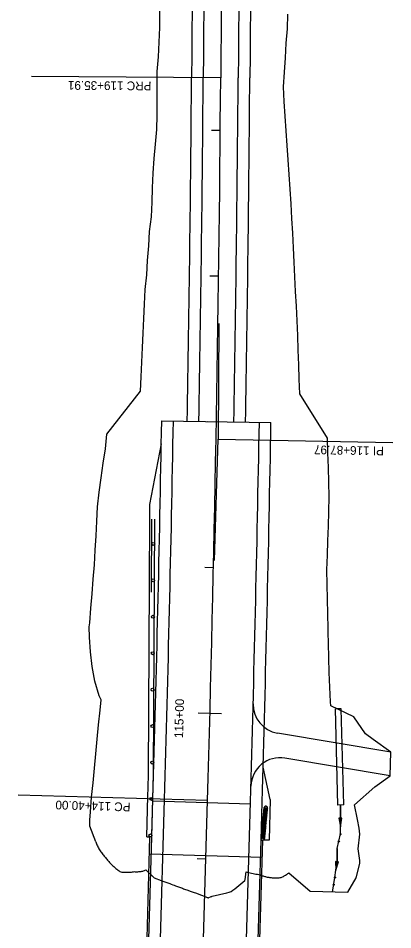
# Model space of a CAD drawing. Extents: x 1441466 to 1476381, y 2042742 to 2057194.
# Drawn here: x 1445981 to 1446238, y 2044108 to 2044733 of the extents above; entities that cross this region are included whole.
import ezdxf

# ---------------------------------------------------------------- set-up
doc = ezdxf.new("R2010")
doc.units = 0
for name, color, linetype in [('Level 43', 7, 'Continuous'), ('R_Bridge', 7, 'Continuous'), ('R_Guardrail', 7, 'Continuous'), ('R_Horz Alg', 7, 'Continuous'), ('R_Horz Alg Annot', 7, 'Continuous'), ('R_Horz Alg Stationing', 7, 'Continuous'), ('R_Impact Attenuator', 7, 'Continuous'), ('R_Proposed Const Limits', 7, 'Continuous'), ('R_Proposed Road', 7, 'Continuous'), ('R_Shld', 7, 'Continuous'), ('R_Special Ditch', 7, 'Continuous')]:
    doc.layers.add(name, color=color, linetype=linetype)

msp = doc.modelspace()

# ---------------------------------------------------------------- linework, layer by layer
at = {"layer": 'Level 43'}
for p, q in [((1446203.02, 2044259.75), (1446199.03, 2044259.65)), ((1446200.63, 2044193.67), (1446199.03, 2044259.65)), ((1446204.63, 2044193.77), (1446203.02, 2044259.75)), ((1446204.63, 2044193.77), (1446200.63, 2044193.67))]:
    msp.add_line(p, q, dxfattribs=at)
at = {"layer": 'R_Bridge'}
for p, q in [((1446140.6, 2044194.41), (1446073.63, 2044196.35)), ((1446068.06, 2044047.95), (1446071.67, 2044171.9)), ((1446069.31, 2044047.92), (1446072.92, 2044171.86)), ((1446072.92, 2044171.86), (1446071.67, 2044171.9)), ((1446144.28, 2044045.74), (1446147.88, 2044169.68)), ((1446145.53, 2044045.7), (1446149.13, 2044169.65)), ((1446147.88, 2044169.68), (1446149.13, 2044169.65)), ((1446148.78, 2044157.65), (1446071.32, 2044159.91))]:
    msp.add_line(p, q, dxfattribs=at)
at = {"layer": 'R_Guardrail'}
msp.add_line((1446072.74, 2044339.83), (1446072.97, 2044389.77), dxfattribs=at)
msp.add_lwpolyline([(1446072.94, 2044172.87), (1446073.67, 2044197.86), (1446074.16, 2044214.97), (1446074.17, 2044215.05), (1446074.97, 2044389.76)], dxfattribs=at)
for centre in [(1446073.89, 2044372.85), (1446073.77, 2044347.85), (1446073.66, 2044322.85), (1446073.55, 2044297.85), (1446073.43, 2044272.85), (1446073.32, 2044247.85), (1446073.2, 2044222.86), (1446072.67, 2044197.89), (1446071.95, 2044172.89)]:
    msp.add_circle(centre, 1, dxfattribs=at)
at = {"layer": 'R_Horz Alg'}
msp.add_line((1446106.5, 2044036.83), (1446111.16, 2044196.76), dxfattribs=at)
for centre, start, end in [((1469037.89, 2044521.83), 178.333333, 179.573112), ((1423202.54, 2044863.34), 358.333333, 359.573112)]:
    msp.add_arc(centre, 22918.31, start, end, dxfattribs=at)
at = {"layer": 'R_Horz Alg Annot'}
for p in [(1446118.96, 2044523.98), (1446115.95, 2044361.46)]:
    msp.add_line(p, (1446118.37, 2044444.62), dxfattribs=at)
for points in [[(1446120.22, 2044692.58), (1445990.22, 2044693.55)], [(1446118.37, 2044444.62), (1446238.35, 2044442.43)], [(1446111.16, 2044196.76), (1445981.21, 2044200.54)]]:
    msp.add_lwpolyline(points, dxfattribs=at)
at = {"layer": 'R_Horz Alg Stationing'}
for points in [[(1446113.92, 2044656.73), (1446119.92, 2044656.67)], [(1446112.8, 2044556.76), (1446118.8, 2044556.68)], [(1446111.24, 2044456.8), (1446117.24, 2044456.69)], [(1446109.25, 2044356.84), (1446115.25, 2044356.71)], [(1446104.83, 2044256.95), (1446120.82, 2044256.53)], [(1446104, 2044156.95), (1446109.99, 2044156.78)]]:
    msp.add_lwpolyline(points, dxfattribs=at)
at = {"layer": 'R_Impact Attenuator'}
for p, q in [((1446148.02, 2044169.8), (1446150.1, 2044192.04)), ((1446150.26, 2044169.59), (1446152.34, 2044191.83)), ((1446151.19, 2044192.94), (1446151.44, 2044192.91))]:
    msp.add_line(p, q, dxfattribs=at)
for centre in [(1446150.6, 2044191.37), (1446151.72, 2044191.27), (1446150.08, 2044185.77), (1446150.18, 2044186.89), (1446150.29, 2044188.01), (1446150.39, 2044189.13), (1446150.5, 2044190.25), (1446151.2, 2044185.67), (1446151.3, 2044186.79), (1446151.41, 2044187.91), (1446151.51, 2044189.03), (1446151.62, 2044190.15), (1446149.45, 2044179.05), (1446149.55, 2044180.17), (1446149.66, 2044181.29), (1446149.76, 2044182.41), (1446149.87, 2044183.53), (1446149.97, 2044184.65), (1446150.57, 2044178.95), (1446150.67, 2044180.07), (1446150.78, 2044181.19), (1446150.88, 2044182.31), (1446150.99, 2044183.43), (1446151.09, 2044184.55), (1446148.92, 2044173.45), (1446149.03, 2044174.57), (1446149.13, 2044175.69), (1446149.24, 2044176.81), (1446149.34, 2044177.93), (1446150.04, 2044173.35), (1446150.15, 2044174.47), (1446150.25, 2044175.59), (1446150.36, 2044176.71), (1446150.46, 2044177.83), (1446148.71, 2044171.21), (1446148.71, 2044171.21), (1446148.82, 2044172.33), (1446149.83, 2044171.11), (1446149.83, 2044171.11), (1446149.94, 2044172.23)]:
    msp.add_circle(centre, 0.563, dxfattribs=at)
for centre, start, end in [((1446151.09, 2044191.94), 84.65511, 174.65511), ((1446151.34, 2044191.92), 354.65511, 84.65511)]:
    msp.add_arc(centre, 1, start, end, dxfattribs=at)
at = {"layer": 'R_Proposed Const Limits'}
for points in [[(1446078.5, 2044727.04), (1446078.45, 2044737.06), (1446078.61, 2044747.08), (1446078.72, 2044757.1), (1446078.88, 2044767.12)], [(1446211.56, 2044254.13), (1446195.84, 2044261.72), (1446195.68, 2044264.59), (1446195.12, 2044274.64), (1446194.74, 2044284.69), (1446194.49, 2044294.73), (1446194.2, 2044304.78), (1446194.04, 2044311.96), (1446193.98, 2044314.82), (1446193.81, 2044324.86), (1446193.59, 2044334.9), (1446193.28, 2044344.95), (1446193.18, 2044354.99), (1446193.5, 2044365.02), (1446193.82, 2044375.05), (1446194.11, 2044385.08), (1446194.4, 2044395.11), (1446194.63, 2044405.14), (1446194.45, 2044415.18), (1446194.21, 2044425.22), (1446193.85, 2044435.26), (1446193.5, 2044445.3), (1446174.54, 2044475.73), (1446174.18, 2044485.76), (1446173.86, 2044495.79), (1446173.5, 2044505.82), (1446173.12, 2044515.85), (1446172.75, 2044525.88), (1446172.22, 2044535.91), (1446171.64, 2044545.95), (1446171.16, 2044555.98), (1446170.68, 2044566.01), (1446170.2, 2044576.04), (1446169.67, 2044586.07), (1446169.14, 2044596.09), (1446168.69, 2044606.12), (1446167.91, 2044616.15), (1446167.3, 2044626.18), (1446166.52, 2044636.21), (1446165.92, 2044646.24), (1446165.15, 2044656.26), (1446164.56, 2044666.29), (1446163.79, 2044676.31), (1446163.38, 2044686.34), (1446164.1, 2044696.34), (1446164.69, 2044706.31), (1446165.11, 2044716.29), (1446165.98, 2044726.26), (1446166.32, 2044736.24)], [(1446034.49, 2044168.54), (1446030.28, 2044179.11), (1446030.36, 2044183.27), (1446030.74, 2044189.1), (1446031.59, 2044199.08), (1446032.61, 2044209.02), (1446033.61, 2044218.96), (1446034.39, 2044228.91), (1446035.43, 2044238.85), (1446036.26, 2044248.8), (1446037.57, 2044258.73), (1446038.06, 2044265.85), (1446036.86, 2044268.72), (1446033.91, 2044278.77), (1446032.01, 2044288.78), (1446030.87, 2044298.78), (1446030.25, 2044308.76), (1446030.03, 2044315.89), (1446030.28, 2044318.73), (1446031.11, 2044328.67), (1446031.93, 2044338.62), (1446032.74, 2044348.57), (1446033.6, 2044358.52), (1446034.12, 2044368.47), (1446034.62, 2044378.43), (1446035.09, 2044388.38), (1446035.67, 2044398.34), (1446036.82, 2044408.28), (1446038.24, 2044418.22), (1446039.63, 2044428.16), (1446041.15, 2044438.1), (1446042.01, 2044448.06), (1446065.18, 2044477.57), (1446065.68, 2044487.54), (1446066.15, 2044497.51), (1446066.61, 2044507.48), (1446067.05, 2044517.46), (1446067.49, 2044527.43), (1446067.92, 2044537.4), (1446068.34, 2044547.37), (1446069.52, 2044557.34), (1446069.89, 2044567.31), (1446070.8, 2044577.28), (1446071.37, 2044587.25), (1446072.74, 2044597.22), (1446073.07, 2044607.19), (1446073.41, 2044617.17), (1446073.8, 2044627.15), (1446074.45, 2044637.12), (1446075.4, 2044647.09), (1446076.4, 2044657.06), (1446076.6, 2044667.04), (1446076.58, 2044677.03), (1446076.7, 2044687.01), (1446076.6, 2044697), (1446077.59, 2044707.01), (1446078.05, 2044717.03), (1446078.5, 2044727.04)], [(1446237.12, 2044229.88), (1446224.86, 2044238.66), (1446219.73, 2044242.46), (1446211.56, 2044254.13)], [(1446207.54, 2044133.93), (1446213.15, 2044143.7), (1446215.7, 2044153.7), (1446215.65, 2044155.71), (1446214.52, 2044163.74), (1446215.66, 2044173.71), (1446215.26, 2044177.89), (1446214.15, 2044183.76), (1446212.01, 2044193.83), (1446225.95, 2044206.31), (1446236.66, 2044213.73)], [(1446034.49, 2044168.54), (1446034.71, 2044167.89), (1446034.97, 2044167.15), (1446035.24, 2044166.43), (1446035.53, 2044165.71), (1446035.84, 2044165), (1446036.22, 2044164.31), (1446036.63, 2044163.65), (1446037.05, 2044162.99), (1446037.48, 2044162.35), (1446037.92, 2044161.72), (1446038.37, 2044161.1), (1446038.82, 2044160.49), (1446039.29, 2044159.9), (1446039.76, 2044159.32), (1446040.24, 2044158.75), (1446040.72, 2044158.19), (1446041.21, 2044157.65), (1446041.67, 2044157.1), (1446042.09, 2044156.53), (1446042.52, 2044155.98), (1446042.96, 2044155.43), (1446043.4, 2044154.9), (1446043.86, 2044154.37), (1446044.32, 2044153.86), (1446044.8, 2044153.35), (1446045.28, 2044152.86), (1446045.77, 2044152.38), (1446046.26, 2044151.91), (1446046.77, 2044151.45), (1446047.28, 2044151), (1446047.8, 2044150.57), (1446048.32, 2044150.14), (1446048.85, 2044149.73), (1446049.39, 2044149.33), (1446049.94, 2044148.94), (1446050.49, 2044148.57), (1446051.04, 2044148.2), (1446051.6, 2044147.85), (1446052.36, 2044147.74), (1446053.14, 2044147.69), (1446053.9, 2044147.65), (1446054.66, 2044147.63), (1446055.41, 2044147.62), (1446056.14, 2044147.62), (1446056.87, 2044147.64), (1446057.58, 2044147.68), (1446058.28, 2044147.72), (1446058.98, 2044147.78), (1446059.66, 2044147.85), (1446060.33, 2044147.93), (1446060.99, 2044148.02), (1446061.58, 2044148), (1446062.16, 2044147.98), (1446062.74, 2044147.98), (1446063.32, 2044148), (1446063.9, 2044148.03), (1446064.47, 2044148.07), (1446065.04, 2044148.14), (1446065.6, 2044148.21), (1446066.15, 2044148.3), (1446066.7, 2044148.4), (1446067.26, 2044148.6), (1446067.82, 2044148.84), (1446068.36, 2044149.09), (1446068.82, 2044149.3)], [(1446068.82, 2044149.29), (1446073.63, 2044144.65), (1446074.11, 2044144.23), (1446074.62, 2044143.86), (1446075.17, 2044143.54), (1446075.75, 2044143.27), (1446078.14, 2044142.31), (1446078.74, 2044142.07), (1446079.34, 2044141.84), (1446079.94, 2044141.62), (1446080.55, 2044141.41), (1446085.32, 2044139.79), (1446086.32, 2044139.45), (1446087.31, 2044139.09), (1446088.3, 2044138.73), (1446089.29, 2044138.36), (1446093.94, 2044136.58), (1446094.68, 2044136.31), (1446095.41, 2044136.04), (1446096.16, 2044135.77), (1446096.9, 2044135.51), (1446099.88, 2044134.49), (1446100.62, 2044134.23), (1446101.36, 2044133.96), (1446102.1, 2044133.69), (1446102.83, 2044133.41), (1446111.06, 2044130.2), (1446111.34, 2044130.12), (1446111.62, 2044130.1), (1446111.9, 2044130.14), (1446112.18, 2044130.25), (1446113.28, 2044130.77), (1446113.56, 2044130.89), (1446113.84, 2044131), (1446114.13, 2044131.09), (1446114.42, 2044131.17), (1446124.47, 2044133.45), (1446125.93, 2044133.87), (1446127.31, 2044134.46), (1446128.6, 2044135.21), (1446129.81, 2044136.13), (1446136.73, 2044142.06), (1446136.77, 2044142.09), (1446136.8, 2044142.13), (1446136.84, 2044142.17), (1446136.87, 2044142.21), (1446137, 2044142.37), (1446137.03, 2044142.41), (1446137.05, 2044142.45), (1446137.07, 2044142.5), (1446137.08, 2044142.55), (1446137.79, 2044147.81)], [(1446137.79, 2044147.81), (1446138.42, 2044147.58), (1446139.42, 2044147.38), (1446140.41, 2044147.19), (1446141.4, 2044146.99), (1446142.4, 2044146.8), (1446143.39, 2044146.6), (1446144.39, 2044146.41), (1446145.38, 2044146.21), (1446146.38, 2044146.02), (1446147.37, 2044145.82), (1446147.39, 2044145.82), (1446147.41, 2044145.81), (1446147.43, 2044145.81), (1446147.82, 2044145.63), (1446148.32, 2044145.44), (1446148.83, 2044145.26), (1446149.35, 2044145.09), (1446149.87, 2044144.92), (1446150.4, 2044144.76), (1446150.94, 2044144.61), (1446151.49, 2044144.47), (1446152.04, 2044144.34), (1446152.6, 2044144.23), (1446153.17, 2044144.14), (1446153.74, 2044144.05), (1446154.31, 2044143.97), (1446154.89, 2044143.91), (1446155.48, 2044143.85), (1446156.07, 2044143.81), (1446156.67, 2044143.78), (1446157.27, 2044143.76), (1446157.88, 2044143.75), (1446158.49, 2044143.76), (1446159.11, 2044143.77), (1446159.73, 2044143.8), (1446160.35, 2044143.85), (1446160.98, 2044143.9), (1446161.61, 2044143.97), (1446162.17, 2044144.18), (1446162.7, 2044144.46), (1446163.22, 2044144.76), (1446163.74, 2044145.06), (1446164.26, 2044145.37), (1446164.77, 2044145.68), (1446165.28, 2044146), (1446165.78, 2044146.33), (1446166.27, 2044146.67), (1446166.76, 2044147.02), (1446166.97, 2044147.17)], [(1446166.97, 2044147.17), (1446181.71, 2044134.68), (1446207.54, 2044133.93)]]:
    msp.add_lwpolyline(points, dxfattribs=at)
at = {"layer": 'R_Proposed Road'}
for p, q in [((1446079.75, 2044457.36), (1446154.74, 2044456.02)), ((1446237.12, 2044229.88), (1446159.18, 2044242.99)), ((1446236.66, 2044213.73), (1446237.12, 2044229.88)), ((1446236.66, 2044213.73), (1446164.27, 2044225.91)), ((1446072.92, 2044171.86), (1446073.67, 2044197.85)), ((1446077.01, 2044037.69), (1446081.67, 2044197.62)), ((1446135.99, 2044035.97), (1446140.64, 2044195.9)), ((1446147.88, 2044169.68), (1446148.64, 2044195.67))]:
    msp.add_line(p, q, dxfattribs=at)
for centre, radius, start, end in [((1469037.89, 2044521.83), 22938.31, 178.333333, 179.573112), ((1469037.89, 2044521.83), 22930.31, 178.333333, 179.573112), ((1469037.89, 2044521.83), 22906.31, 178.333333, 179.573112), ((1469037.89, 2044521.83), 22898.31, 178.333333, 179.573112), ((1423202.54, 2044863.34), 22898.31, 358.983333, 359.573112), ((1423202.54, 2044863.34), 22906.31, 358.983333, 359.573112), ((1423202.54, 2044863.34), 22930.31, 358.983333, 359.573112), ((1423202.54, 2044863.34), 22938.31, 358.983333, 359.573112), ((1423202.54, 2044863.34), 22880.81, 358.333333, 358.983333), ((1423202.54, 2044863.34), 22888.81, 358.333333, 358.983333), ((1423202.54, 2044863.34), 22947.81, 358.333333, 358.983333), ((1423202.54, 2044863.34), 22955.81, 358.333333, 358.983333), ((1446162.5, 2044262.72), 20, 178.50152, 260.44833), ((1446160.95, 2044206.19), 20, 80.44833, 178.36045)]:
    msp.add_arc(centre, radius, start, end, dxfattribs=at)
at = {"layer": 'R_Shld'}
for p, q in [((1446071.67, 2044399.76), (1446079.46, 2044441.41)), ((1446070.67, 2044215.07), (1446071.47, 2044389.78)), ((1446154.2, 2044197.51), (1446149.33, 2044219.71)), ((1446069.42, 2044171.97), (1446070.23, 2044199.95)), ((1446154.2, 2044197.51), (1446153.38, 2044169.52)), ((1446069.42, 2044171.97), (1446071.67, 2044171.9)), ((1446153.38, 2044169.52), (1446149.13, 2044169.65))]:
    msp.add_line(p, q, dxfattribs=at)
for radius, start, end in [(22873.81, 358.808708, 358.833708), (22877.31, 358.333333, 358.371208)]:
    msp.add_arc((1423202.6, 2044865.33), radius, start, end, dxfattribs=at)
at = {"layer": 'R_Special Ditch'}
for p, q in [((1446203.48, 2044184.71), (1446201.37, 2044184.72)), ((1446201.37, 2044184.72), (1446202.42, 2044178.71)), ((1446202.42, 2044178.71), (1446203.48, 2044184.71)), ((1446201.15, 2044154.77), (1446199.06, 2044155.05)), ((1446199.06, 2044155.05), (1446199.3, 2044148.96)), ((1446199.3, 2044148.96), (1446201.15, 2044154.77))]:
    msp.add_line(p, q, dxfattribs=at)
for points in [[(1446196.91, 2044133.96), (1446198.62, 2044143.95), (1446199.98, 2044153.97), (1446200.23, 2044156.09), (1446200.27, 2044164), (1446202.4, 2044173.94), (1446202.41, 2044178.32), (1446202.43, 2044184.16), (1446202.43, 2044193.71)], [(1446202.43, 2044193.71), (1446202.43, 2044184.16), (1446202.42, 2044178.71)], [(1446200.27, 2044163.9), (1446200.23, 2044156.09), (1446199.98, 2044153.97), (1446199.3, 2044148.96)], [(1446200.27, 2044163.94), (1446200.27, 2044163.9)], [(1446196.94, 2044134.11), (1446196.91, 2044133.96)], [(1446196.94, 2044134.15), (1446196.94, 2044134.11)]]:
    msp.add_lwpolyline(points, dxfattribs=at)
for centre in [(1446202.39, 2044173.71), (1446201.34, 2044168.81), (1446198.66, 2044144), (1446197.82, 2044139.06)]:
    msp.add_circle(centre, 0.375, dxfattribs=at)

# ---------------------------------------------------------------- texts
at = {"layer": 'R_Horz Alg Annot'}
for s, rotation, p in [('PRC 119+35.91', 179.57311, (1446072.69, 2044689.94)), ('PI 116+87.97', 178.95322, (1446232.29, 2044439.54)), ('PC 114+40.00', 178.33333, (1446058.38, 2044195.3))]:
    msp.add_text(s, height=6, rotation=rotation, dxfattribs=at).set_placement(p)
at = {"layer": 'R_Horz Alg Stationing'}
msp.add_text('115+00', height=6, rotation=88.48333, dxfattribs=at).set_placement((1446094.36, 2044239.58))

doc.saveas('drawing.dxf')
